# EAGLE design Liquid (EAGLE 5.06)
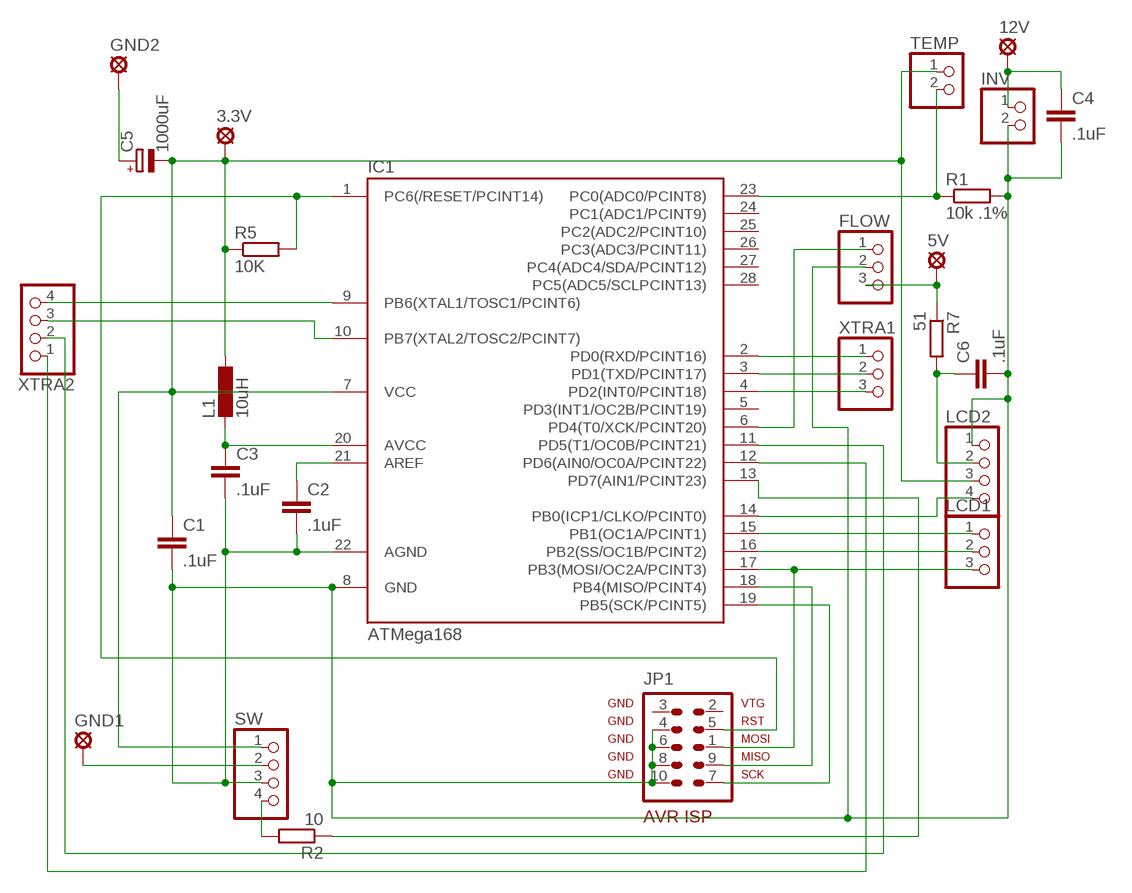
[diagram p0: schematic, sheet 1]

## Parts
3.3V  LSP10  [LSP10]
5V  LSP10  [LSP10]
12V  LSP10  [LSP10]
C1  .1uF  C-EU025-025X050  [C025-025X050]
C2  .1uF  C-EU025-025X050  [C025-025X050]
C3  .1uF  C-EU050-024X044  [C050-024X044]
C4  .1uF  C-EU025-025X050  [C025-025X050]
C5  1000uF  CPOL-EUE3.5-10  [E3,5-10]
C6  .1uF  C-EU025-025X050  [C025-025X050]
FLOW  PINHD-1X3  [1X03]
GND1  LSP10  [LSP10]
GND2  LSP10  [LSP10]
IC1  ATMega168  MEGA48/88/168-PU  [DIL28-3]
INV  PINHD-1X2  [1X02]
JP1  ISP  AVR-ISP-10  [AVR-ISP-10]
L1  10uH  L-EU0207/15  [0207/15]
LCD1  PINHD-1X3  [1X03]
LCD2  PINHD-1X4  [1X04]
R1  10k .1%  R-EU_0207/10  [0207/10]
R2  10  R-EU_0207/10  [0207/10]
R5  10K  R-EU_0207/10  [0207/10]
R7  51  R-EU_0309/12  [0309/12]
SW  PINHD-1X4  [1X04]
TEMP  PINHD-1X2  [1X02]
XTRA1  PINHD-1X3  [1X03]
XTRA2  PINHD-1X4  [1X04]

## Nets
N$1: C5.+ GND2.MP
N$2: FLOW.1 IC1.6(PD4(T0/XCK/PCINT20))
N$3: C2.1 IC1.21(AREF)
N$4: IC1.19(PB5(SCK/PCINT5)) JP1.7
N$5: C3.1 IC1.20(AVCC) L1.2
N$6: C1.2 C2.2 C3.2 C4.2 C6.2 FLOW.2 IC1.8(GND) IC1.22(AGND) INV.2 JP1.4 JP1.6 JP1.8 JP1.10 LCD2.1 R1.2 SW.3
N$7: GND1.MP SW.2
N$8: IC1.17(PB3(MOSI/OC2A/PCINT3)) JP1.1 LCD1.3
N$9: IC1.1(PC6(/RESET/PCINT14)) JP1.5 R5.2
N$10: IC1.16(PB2(SS/OC1B/PCINT2)) LCD1.2
N$11: IC1.15(PB1(OC1A/PCINT1)) LCD1.1
N$12: IC1.14(PB0(ICP1/CLKO/PCINT0)) LCD2.4
N$13: IC1.23(PC0(ADC0/PCINT8)) R1.1 TEMP.2
N$14: 3.3V.MP C1.1 C5.- IC1.7(VCC) L1.1 LCD2.3 R5.1 SW.1 TEMP.1
N$15: 5V.MP FLOW.3 R7.1
N$16: R2.2 SW.4
N$17: IC1.13(PD7(AIN1/PCINT23)) R2.1
N$18: C6.1 LCD2.2 R7.2
N$19: 12V.MP C4.1 INV.1
N$23: IC1.18(PB4(MISO/PCINT4)) JP1.9
N$24: IC1.10(PB7(XTAL2/TOSC2/PCINT7)) XTRA2.3
N$25: IC1.9(PB6(XTAL1/TOSC1/PCINT6)) XTRA2.4
N$26: IC1.11(PD5(T1/OC0B/PCINT21)) XTRA2.2
N$27: IC1.12(PD6(AIN0/OC0A/PCINT22)) XTRA2.1
N$28: IC1.2(PD0(RXD/PCINT16)) XTRA1.1
N$29: IC1.3(PD1(TXD/PCINT17)) XTRA1.2
N$30: IC1.4(PD2(INT0/PCINT18)) XTRA1.3
Unconnected: IC1.5(PD3(INT1/OC2B/PCINT19)) IC1.24(PC1(ADC1/PCINT9)) IC1.25(PC2(ADC2/PCINT10)) IC1.26(PC3(ADC3/PCINT11)) IC1.27(PC4(ADC4/SDA/PCINT12)) IC1.28(PC5(ADC5/SCLPCINT13)) JP1.2 JP1.3

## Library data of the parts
3.3V 5V 12V GND1 GND2 = solpad:LSP10: SOLDER PAD
C1-C4 C6 = rcl:C-EU: CAPACITOR, European symbol
C5 = rcl:CPOL-EU: POLARIZED CAPACITOR, European symbol
FLOW LCD1 XTRA1 = pinhead:PINHD-1X3: PIN HEADER
IC1 = avr-4:MEGA48/88/168-PU
INV TEMP = pinhead:PINHD-1X2: PIN HEADER
JP1 = avr-4:AVR-ISP-10: AVR ISP-10 Serial Programming Header
L1 = rcl:L-EU: INDUCTOR, European symbol
LCD2 SW XTRA2 = pinhead:PINHD-1X4: PIN HEADER
R1 R2 R5 R7 = rcl:R-EU_: RESISTOR, European symbol

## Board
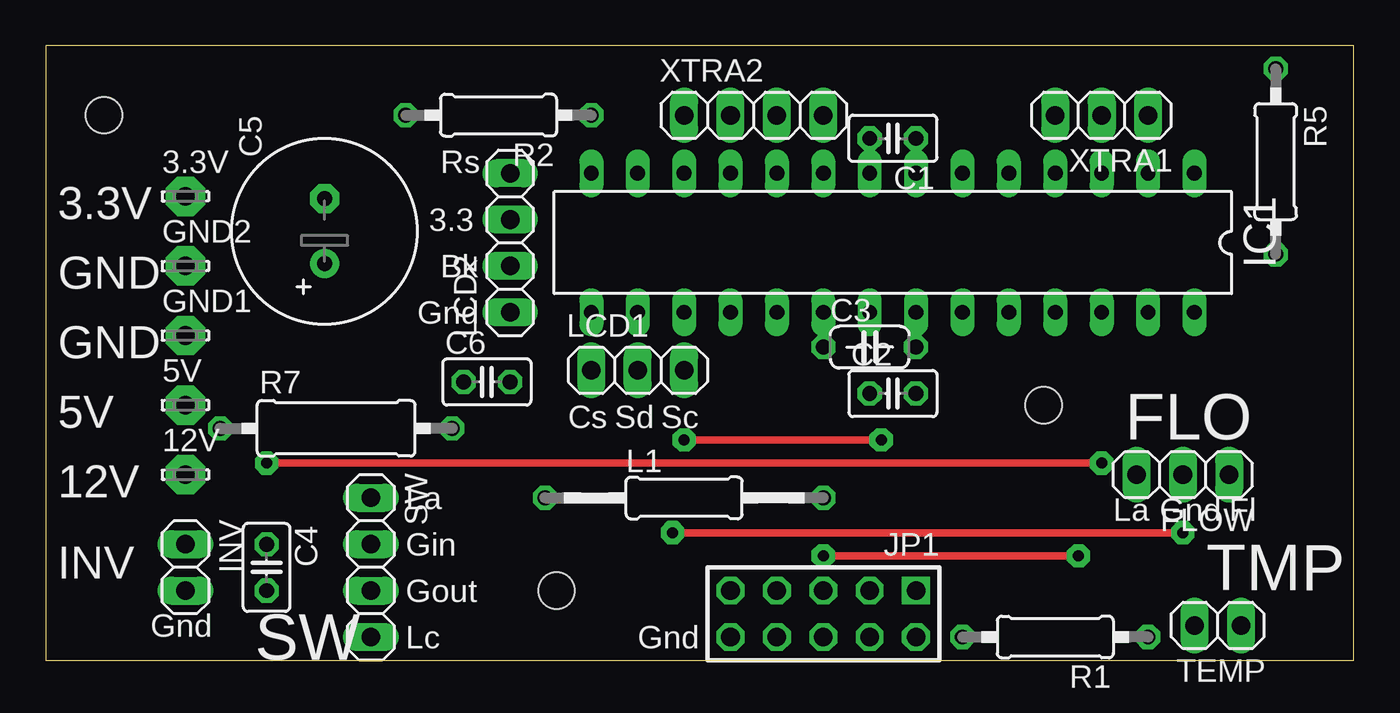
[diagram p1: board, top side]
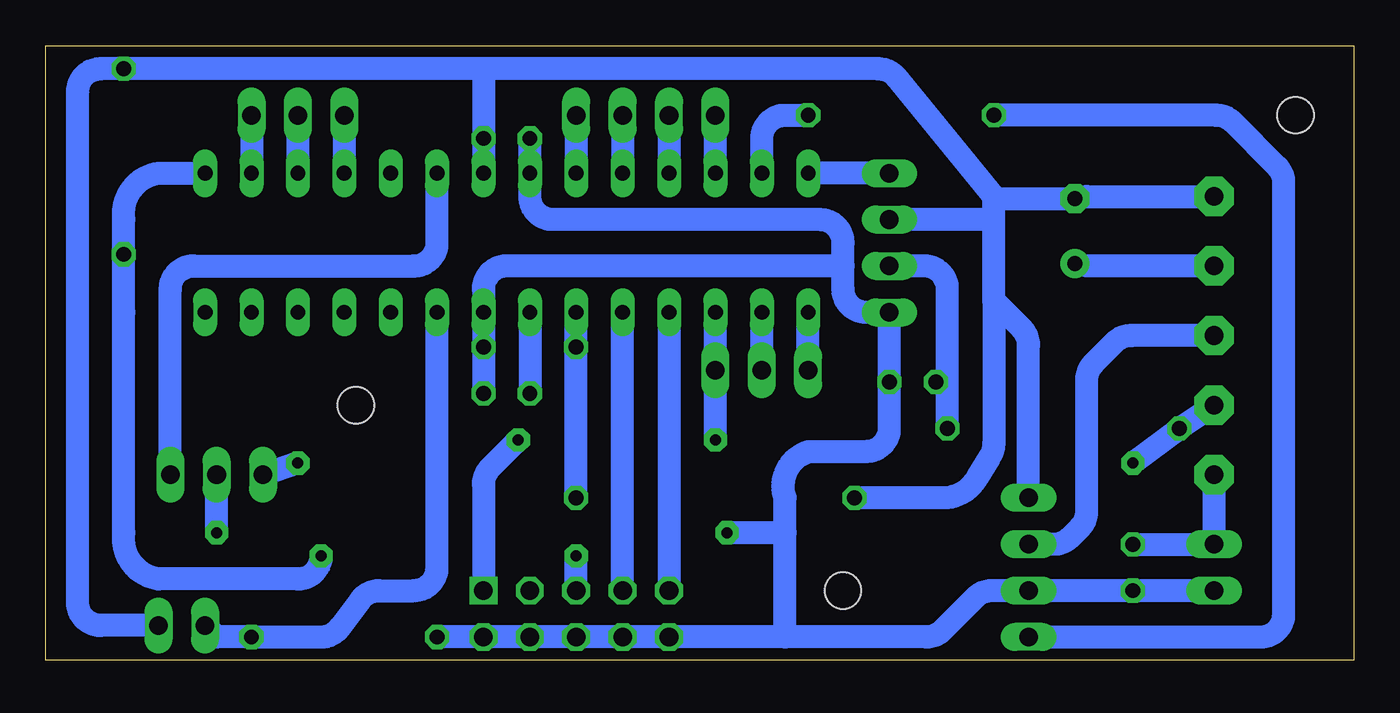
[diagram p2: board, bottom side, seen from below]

Size 71.62 x 33.64 mm. Coordinates in mm from the lower left corner, seen from the top.
Outline: 0,0 71.62,0 71.62,33.64 0,33.64 0,0
Copper layers (1*16): Top 0.035mm / dielectric 1.5mm / Bottom 0.035mm
Design rules "default": minimum track width 10mil, minimum drill 24mil, track to track 8mil, track to pad 8mil, pad to pad 8mil, via to via 8mil, smd to smd 8mil, copper to edge 40mil, drill to drill 8mil, minimum pad ring 10mil, minimum via ring 8mil, stop-mask expansion 4mil, vias tented up to drill 0mil, thermal gap 10mil
Holes 2 mm at 3.2,29.84 54.64,13.96 27.97,3.81
tRestrict: area 25.7,1.5 to 30.3,6.1; area 0.9,27.6 to 5.5,32.1; area 52.3,11.7 to 56.9,16.3

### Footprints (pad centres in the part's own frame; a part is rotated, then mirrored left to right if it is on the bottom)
LSP10 = drill 1.016 pad 2.159 octagon: MP 0,0
C025-025X050 = drill 0.813 octagon: 1 -1.27,0; 2 1.27,0
C050-024X044 = drill 0.813 octagon: 1 -2.54,0; 2 2.54,0
E3,5-10 = drill 0.813 pad 1.6 round: + -1.778,0 | drill 0.813 pad 1.6 octagon: - 1.778,0
1X03 = drill 1.016 long: 1 -2.54,0; 2 0,0; 3 2.54,0
DIL28-3 = drill 0.813 long: 1 -16.51,-3.81; 2 -13.97,-3.81; 3 -11.43,-3.81; 4 -8.89,-3.81; 5 -6.35,-3.81; 6 -3.81,-3.81; 7 -1.27,-3.81; 8 1.27,-3.81; 9 3.81,-3.81; 10 6.35,-3.81; 11 8.89,-3.81; 12 11.43,-3.81; 13 13.97,-3.81; 14 16.51,-3.81; 15 16.51,3.81; 16 13.97,3.81; 17 11.43,3.81; 18 8.89,3.81; 19 6.35,3.81; 20 3.81,3.81; 21 1.27,3.81; 22 -1.27,3.81; 23 -3.81,3.81; 24 -6.35,3.81; 25 -8.89,3.81; 26 -11.43,3.81; 27 -13.97,3.81; 28 -16.51,3.81
1X02 = drill 1.016 long: 1 -1.27,0; 2 1.27,0
AVR-ISP-10 = drill 1.016 square: 1 -5.08,-1.27 | drill 1.016 octagon: 2 -5.08,1.27; 3 -2.54,-1.27; 4 -2.54,1.27; 5 0,-1.27; 6 0,1.27; 7 2.54,-1.27; 8 2.54,1.27; 9 5.08,-1.27; 10 5.08,1.27
0207/15 = drill 0.813 octagon: 1 -7.62,0; 2 7.62,0
1X04 = drill 1.016 long: 1 -3.81,0; 2 -1.27,0; 3 1.27,0; 4 3.81,0
0207/10 = drill 0.813 octagon: 1 -5.08,0; 2 5.08,0
0309/12 = drill 0.813 octagon: 1 -6.35,0; 2 6.35,0

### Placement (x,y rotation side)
3.3V  7.65,25.39 0 top
5V  7.65,13.96 0 top
12V  7.65,10.15 0 top
C1  46.38,28.57 180 top
C2  46.38,14.6 0 top
C3  45.11,17.14 0 top
C4  12.09,5.08 270 top
C5  15.27,23.49 90 top
C6  24.16,15.23 0 top
FLOW  62.26,10.15 180 top
GND1  7.65,17.78 0 top
GND2  7.65,21.59 0 top
IC1  46.38,22.86 180 top
INV  7.65,5.08 270 top
JP1  42.57,2.54 180 top
L1  34.95,8.88 0 top
LCD1  32.41,15.87 0 top
LCD2  25.43,22.86 90 top
R1  55.27,1.27 180 top
R2  24.79,29.84 180 top
R5  67.34,27.3 270 top
R7  15.9,12.69 0 top
SW  17.81,5.08 270 top
TEMP  64.16,1.9 180 top
XTRA1  57.81,29.84 180 top
XTRA2  38.76,29.84 0 top

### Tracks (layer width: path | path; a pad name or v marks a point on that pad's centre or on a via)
N$1
  Bottom 1.27: GND2.MP 14.63,21.59 C5.+
N$2
  Bottom 1.27: IC1.6 50.19,22.86 arc90 51.46,21.59 63.53,21.59 arc-90 64.8,20.32 FLOW.1
N$3
  Bottom 1.27: IC1.21 C2.1
N$4
  Bottom 1.27: JP1.7 IC1.19
N$5
  Bottom 1.27: IC1.20 C3.1 L1.2
N$6  (via drill 0.6 pad 1.27)
  Top 0.406: v34.32,6.98 v62.26,6.98
  Bottom 1.27: C1.2 IC1.8 45.11,25.39 arc-90 43.84,24.12 29.24,24.12 arc90 27.97,22.86 27.97,21.59 | 31.14,1.27 JP1.10 JP1.8 JP1.6 JP1.4 R1.2 | 31.14,1.27 31.14,6.98 | 31.14,6.98 31.14,8.88 arc90 29.87,11.42 26.7,11.42 arc-90 25.43,12.69 C6.2 LCD2.1 26.7,19.05 arc90 27.97,20.32 27.97,21.59 | INV.2 C4.2 SW.3 19.82,3.81 arc-45 20.72,3.43 22.51,1.64 arc45 23.41,1.27 31.14,1.27 | IC1.22 C2.2 | IC1.22 C3.2 | 27.97,21.59 46.38,21.59 arc-90 47.65,20.32 IC1.22 | v62.26,6.98 FLOW.2 | 31.14,6.98 v34.32,6.98
N$7
  Bottom 1.27: GND1.MP 12.2,17.78 arc-45 13.1,17.4 14.26,16.24 arc-45 14.63,15.34 14.63,8.14 arc45 15,7.24 15.53,6.72 arc45 16.43,6.34 SW.2
N$8  (via drill 0.6 pad 1.27)
  Top 0.406: v45.75,12.06 v34.95,12.06
  Bottom 1.27: v45.75,12.06 47.28,10.53 arc-45 47.65,9.63 JP1.1 | v34.95,12.06 LCD1.3 IC1.17
N$9  (via drill 0.6 pad 1.27)
  Top 0.406: v42.57,5.71 v56.54,5.71
  Bottom 1.27: JP1.5 v42.57,5.71 | v56.54,5.71 arc90 57.81,4.44 65.43,4.44 arc90 67.34,6.98 67.34,19.05 R5.2 67.34,24.12 arc90 65.43,26.67 IC1.1
N$10
  Bottom 1.27: LCD1.2 IC1.16
N$11
  Bottom 1.27: LCD1.1 IC1.15
N$12
  Bottom 1.27: LCD2.4 IC1.14
N$13
  Bottom 1.27: IC1.23 50.19,5.08 arc90 51.46,3.81 53.37,3.81 arc-53 54.38,3.3 55.52,1.77 arc53 56.54,1.27 R1.1 62.26,1.27 TEMP.2
N$14
  Bottom 1.27: IC1.7 C1.1 47.65,32.38 | 19.71,24.12 19.71,25.39 | 19.71,24.12 LCD2.3 | TEMP.1 68.61,1.9 arc90 69.88,3.17 69.88,31.11 arc90 68.61,32.38 R5.1 47.65,32.38 | 19.71,25.39 25.04,31.91 arc-51 26.03,32.38 47.65,32.38 | 19.71,19.68 19.71,11.85 arc37 19.96,11.09 20.6,10.03 arc53 22.25,8.88 L1.1 | 19.71,19.68 19.71,24.12 | SW.1 17.81,17.25 arc-45 18.18,18.15 19.71,19.68 | 3.3V.MP 14.63,25.39 C5.- 19.71,25.27 19.71,25.39
N$15  (via drill 0.6 pad 1.27)
  Top 0.406: v12.09,10.79 v57.81,10.79
  Bottom 1.27: 5V.MP R7.1 v12.09,10.79 | v57.81,10.79 FLOW.3
N$16
  Bottom 1.27: SW.4 5.11,1.27 arc-90 3.84,2.54 3.84,26.14 arc-45 4.21,27.04 6.64,29.47 arc-45 7.54,29.84 R2.2
N$17
  Bottom 1.27: IC1.13 32.41,28.57 arc90 31.14,29.84 R2.1
N$18
  Bottom 1.27: R7.2 22.25,15.23 | 22.25,15.23 22.25,20.32 arc-90 23.52,21.59 LCD2.2 | 22.25,15.23 C6.1
N$19
  Bottom 1.27: 12V.MP INV.1 C4.1
N$23
  Bottom 1.27: IC1.18 JP1.9
N$24
  Bottom 1.27: XTRA2.3 IC1.10
N$25
  Bottom 1.27: XTRA2.4 IC1.9
N$26
  Bottom 1.27: XTRA2.2 IC1.11
N$27
  Bottom 1.27: IC1.12 XTRA2.1
N$28
  Bottom 1.27: XTRA1.1 IC1.2
N$29
  Bottom 1.27: XTRA1.2 IC1.3
N$30
  Bottom 1.27: XTRA1.3 IC1.4

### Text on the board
tPlace: Rs | 3.3V | 3.3 | Bk | GND | Gnd | GND | 5V | Cs | Sd | Sc | FLO | 12V | La | La | Gnd | Fl | Gin | INV | TMP | Gout | Gnd | Lc | Gnd | SW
